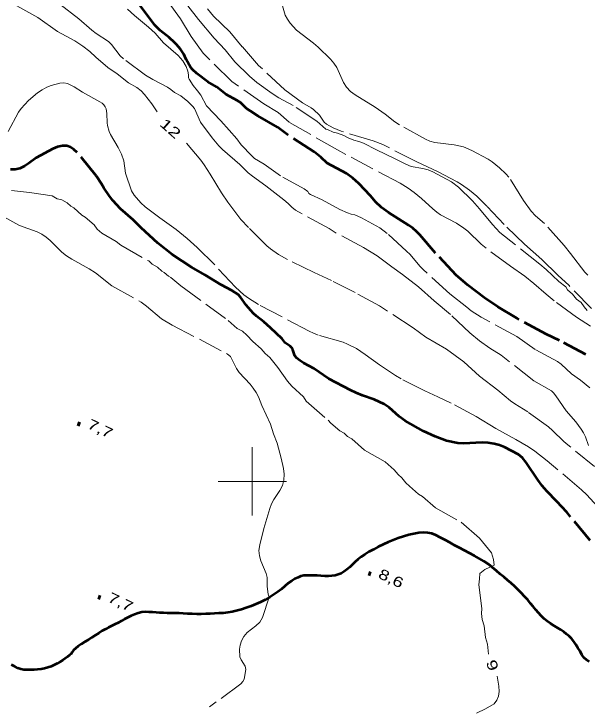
# Model space of a CAD drawing. Extents: x 355726 to 357533, y 5103782 to 5105258.
# Drawn here: x 356465.1 to 356549, y 5104366.5 to 5104468.4 of the extents above; entities that cross this region are included whole.
import ezdxf
from ezdxf.enums import TextEntityAlignment as Align

# ---------------------------------------------------------------- set-up
doc = ezdxf.new("R2010")
doc.units = 0
doc.header["$LTSCALE"] = 0.6
doc.linetypes.add('DASH_DOUBLE_DOT', pattern=[9.2, 5, -1.2, 0.3, -1.2, 0.3, -1.2])
doc.linetypes.add('LONG_DASHED', pattern=[7.5, 6, -1.5])
for name, color, linetype, lineweight in [('1', 7, 'LONG_DASHED', 53), ('2', 7, 'LONG_DASHED', 13), ('3', 7, 'Continuous', 140), ('4', 7, 'DASH_DOUBLE_DOT', 53), ('61', 7, 'Continuous', 13)]:
    doc.layers.add(name, color=color, linetype=linetype, lineweight=lineweight)

msp = doc.modelspace()

# ---------------------------------------------------------------- linework, layer by layer
at = {"layer": '1'}
for points in [[(356548.79, 5104418.59), (356544.98, 5104420.61), (356543.02, 5104421.55), (356538.7, 5104423.87), (356535.92, 5104425.55), (356533.98, 5104426.84), (356531.53, 5104428.7), (356529.84, 5104430.19), (356526.82, 5104433.41), (356524.53, 5104436.09), (356524.03, 5104436.59), (356523.49, 5104437.08), (356522.88, 5104437.51), (356519.92, 5104439.36), (356518.9, 5104440.07), (356518.03, 5104440.92), (356517.31, 5104441.78), (356515.6, 5104443.59), (356514.74, 5104444.36), (356513.79, 5104445.07), (356510.98, 5104446.59), (356510.05, 5104447.46), (356509.06, 5104448.24), (356505.04, 5104450.8), (356503.71, 5104451.86), (356500.82, 5104453.5), (356499.69, 5104454.21), (356499.18, 5104454.59), (356498.26, 5104455.45), (356497.8, 5104455.75), (356496.18, 5104456.63), (356494.76, 5104457.73), (356493.51, 5104458.47), (356491.89, 5104459.68), (356491.25, 5104460.28), (356490.98, 5104460.63), (356490.35, 5104461.76), (356489.99, 5104462.51), (356489.52, 5104463.23), (356488.94, 5104463.92), (356488.6, 5104464.25), (356487.84, 5104464.95), (356486.55, 5104465.99), (356485.76, 5104466.76), (356481.4, 5104472.57)], [(356549.47, 5104391.34), (356546.02, 5104395.48), (356544.58, 5104397.07), (356543.11, 5104398.55), (356542.42, 5104399.36), (356541.78, 5104400.21), (356540.09, 5104402.78), (356539.55, 5104403.44), (356538.96, 5104403.93), (356536.93, 5104404.99), (356536.2, 5104405.3), (356535.39, 5104405.49), (356534.54, 5104405.63), (356533.65, 5104405.68), (356530.91, 5104405.54), (356530.08, 5104405.59), (356528.44, 5104405.95), (356526.75, 5104406.55), (356525.08, 5104407.34), (356522.36, 5104408.88), (356521.48, 5104409.51), (356520.02, 5104410.8), (356519.31, 5104411.3), (356517.85, 5104411.99), (356516.11, 5104412.59), (356515.21, 5104412.94), (356514.36, 5104413.34), (356511.23, 5104415.01), (356509, 5104416.5), (356507.55, 5104417.3), (356506.98, 5104417.67), (356506.52, 5104418.01), (356506.22, 5104418.38), (356505.92, 5104419.24), (356505.75, 5104419.58), (356505.56, 5104419.8), (356504.83, 5104420.3), (356504.37, 5104420.84), (356502.68, 5104422.46), (356501.7, 5104423.33), (356500.6, 5104424.16), (356500.14, 5104424.61), (356499.13, 5104425.8), (356498.3, 5104426.98), (356497.92, 5104427.34), (356497.03, 5104427.92), (356495.47, 5104428.75), (356493.08, 5104430.25), (356491.12, 5104431.33), (356488.29, 5104433.18), (356486.19, 5104434.88), (356483.76, 5104437.09), (356482.59, 5104438.26), (356480.71, 5104439.91), (356479.6, 5104441.09), (356479.1, 5104441.72), (356478.26, 5104442.96), (356477.94, 5104443.55), (356477.22, 5104444.65), (356474.39, 5104448.13), (356473.91, 5104448.59), (356473.4, 5104448.92), (356472.85, 5104449.09), (356472.23, 5104449.09), (356471.51, 5104448.96), (356470.82, 5104448.69), (356468.37, 5104447.34), (356467.28, 5104446.5), (356466.68, 5104446.12), (356466.01, 5104445.79), (356465.33, 5104445.62), (356464.63, 5104445.65)]]:
    msp.add_lwpolyline(points, dxfattribs=at)
at = {"layer": '2'}
for points in [[(356486.07, 5104454.09), (356485.29, 5104455.23), (356484.22, 5104456.63), (356483.75, 5104457.17), (356483.1, 5104457.63), (356481.87, 5104458.34), (356480.21, 5104459.66), (356478.88, 5104460.59), (356477.13, 5104462.08), (356476.24, 5104462.9), (356475.19, 5104463.7), (356474.02, 5104464.46), (356471.52, 5104465.84), (356468.63, 5104467.9), (356465.56, 5104469.61)], [(356549.2, 5104405.26), (356548.75, 5104406.51), (356548.47, 5104407.09), (356548.14, 5104407.63), (356547.33, 5104408.72), (356545.92, 5104410.34), (356544.42, 5104412.54), (356544.08, 5104412.97), (356543.78, 5104413.26), (356541.21, 5104414.73), (356537.18, 5104417.88), (356536.4, 5104418.45), (356534.75, 5104419.51), (356533.25, 5104420.59), (356531.86, 5104421.76), (356528.99, 5104424.42), (356526.62, 5104426.41), (356524.33, 5104428.48), (356522, 5104430.29), (356520.45, 5104431.38), (356518.3, 5104433), (356516.28, 5104434.23), (356512.3, 5104436.34), (356511.25, 5104437.01), (356506.32, 5104439.69), (356505.78, 5104440.13), (356505.24, 5104440.68), (356504.62, 5104441.22), (356502, 5104443.24), (356500.03, 5104444.65), (356499.4, 5104445.17), (356498.18, 5104446.37), (356495.64, 5104448.55), (356495.09, 5104449.09), (356494.13, 5104450.29), (356492.42, 5104452.57), (356491.56, 5104454.57), (356491.27, 5104454.92), (356490.56, 5104455.61), (356489.55, 5104456.41), (356488.63, 5104456.9), (356488.1, 5104457.37), (356487.6, 5104457.68), (356485.46, 5104458.82), (356484.37, 5104459.47), (356481.18, 5104461.84), (356480.69, 5104462.3), (356479.42, 5104463.95), (356478.96, 5104464.37), (356477.16, 5104465.55), (356476.52, 5104466.05), (356474.64, 5104467.69), (356471.84, 5104469.83)], [(356549.49, 5104422.73), (356547.44, 5104424.04), (356544.18, 5104426.43), (356542.99, 5104427.38), (356541.19, 5104428.96), (356539.88, 5104430.03), (356537.8, 5104431.49), (356534.22, 5104434.11), (356533.49, 5104434.73), (356531.54, 5104436.62), (356530.97, 5104437.07), (356529.88, 5104437.79), (356527.56, 5104439.03), (356526.99, 5104439.42), (356526.43, 5104439.87), (356524.78, 5104441.42), (356523.7, 5104442.29), (356522.82, 5104442.9), (356521.63, 5104443.62), (356512.48, 5104448.51), (356505.38, 5104452.58), (356503.8, 5104453.98), (356501.7, 5104455.26), (356497, 5104458.54), (356492.81, 5104462.69), (356491.07, 5104465.09), (356489.51, 5104467.71), (356487.69, 5104470.17)], [(356549.03, 5104425), (356548.56, 5104425.54), (356548.13, 5104426.16), (356547.46, 5104426.69), (356546.86, 5104427.38), (356546.14, 5104428.04), (356545.87, 5104428.46), (356544.84, 5104429.26), (356543.01, 5104431), (356542.06, 5104431.8), (356536.25, 5104436.42), (356535.15, 5104437.58), (356533.26, 5104439.91), (356532.25, 5104441.04), (356530.2, 5104443.04), (356529.18, 5104443.83), (356526.41, 5104445.3), (356525.72, 5104445.61), (356524.96, 5104445.8), (356523.27, 5104446.09), (356522.45, 5104446.41), (356520.93, 5104447.22), (356518.16, 5104448.5), (356516.27, 5104449.51), (356515.59, 5104449.76), (356514.86, 5104449.92), (356514.05, 5104450.26), (356513.42, 5104450.63), (356512.48, 5104450.96), (356511.82, 5104451.11), (356511, 5104451.51), (356510.78, 5104451.57), (356509.45, 5104452.71), (356506, 5104455), (356503.91, 5104456.15), (356502.91, 5104456.76), (356500.67, 5104458.36), (356499.59, 5104459.29), (356497.44, 5104461.42), (356496.02, 5104463.15), (356494.44, 5104464.88), (356492.12, 5104467.61), (356490.58, 5104469.59)], [(356525.34, 5104450.09), (356521.57, 5104452.16), (356520.86, 5104452.63), (356519.46, 5104453.75), (356518, 5104454.75), (356515.08, 5104456.59), (356514.39, 5104457.07), (356513.8, 5104457.69), (356513.37, 5104458.37), (356512.38, 5104460.57), (356511.94, 5104461.2), (356511.44, 5104461.79), (356509.64, 5104463.53), (356508.98, 5104464.11), (356506.48, 5104466.04), (356505.54, 5104467.08), (356505.15, 5104467.63), (356504.84, 5104468.21), (356504.33, 5104469.94)], [(356549.4, 5104413.7), (356548.03, 5104414.79), (356546.72, 5104415.72), (356545.2, 5104417.13), (356544.68, 5104417.54), (356541.42, 5104419.32), (356538.7, 5104421.2), (356533.51, 5104424.01), (356532.04, 5104424.98), (356531.38, 5104425.49), (356528.93, 5104427.45), (356525, 5104430.99), (356524.5, 5104431.5), (356523.1, 5104433.18), (356522.58, 5104433.7), (356519.73, 5104436.29), (356518.68, 5104437.13), (356515.99, 5104438.59), (356515, 5104439.01), (356514.48, 5104439.11), (356513.94, 5104439.29), (356512.81, 5104439.8), (356510.22, 5104441.21), (356508.53, 5104441.99), (356508.28, 5104442.13), (356508.11, 5104442.41), (356507.62, 5104442.8), (356504.14, 5104444.71), (356501.74, 5104446.43), (356500.33, 5104447.26), (356499.93, 5104447.62), (356498.4, 5104449.23), (356497.73, 5104450.13), (356496.62, 5104451.41), (356495.41, 5104452.76), (356493.31, 5104454.98), (356492.47, 5104456.53), (356492.01, 5104457.17), (356491.35, 5104457.95), (356490.78, 5104458.84), (356490.66, 5104459.08), (356490.67, 5104459.51), (356490.56, 5104460.03), (356490.31, 5104460.73), (356489.84, 5104461.53), (356489.15, 5104462.34), (356487.02, 5104464.2), (356485.79, 5104465.58), (356484.83, 5104466.45), (356482.76, 5104468.18), (356481.75, 5104469.09)], [(356549.62, 5104425.3), (356546.36, 5104428.67), (356544.7, 5104430.18), (356542.38, 5104432.45), (356539.85, 5104434.71), (356536.84, 5104437.59), (356534.31, 5104440.28), (356532.84, 5104441.72), (356531.8, 5104442.62), (356530.62, 5104443.46), (356529.98, 5104443.86), (356527.11, 5104445.37), (356524.09, 5104446.75), (356519.13, 5104449.28), (356517.67, 5104449.83), (356513, 5104451.26), (356511.85, 5104451.76), (356510.86, 5104452.3), (356510.5, 5104452.55), (356509.86, 5104453.59), (356508.98, 5104454.4), (356508.62, 5104454.67), (356507.33, 5104455.38), (356504.79, 5104457.3), (356500.93, 5104460.88), (356498.53, 5104463.61), (356496.73, 5104465.8), (356494.32, 5104468.07), (356493.43, 5104469.15)], [(356482.35, 5104442.51), (356481.43, 5104445.09), (356481.2, 5104446.91), (356480.87, 5104447.88), (356480.4, 5104448.88), (356479.27, 5104450.78), (356479.08, 5104451.21), (356478.84, 5104452.07), (356478.78, 5104452.46), (356478.73, 5104453.84), (356478.62, 5104454.51), (356478.48, 5104454.82), (356478.27, 5104455.09), (356478.02, 5104455.37), (356477.72, 5104455.57), (356475.15, 5104456.94), (356473.93, 5104457.74), (356472.99, 5104458.24), (356472.45, 5104458.34), (356471.85, 5104458.28), (356470.59, 5104457.94), (356469.92, 5104457.68), (356469.25, 5104457.3), (356468.58, 5104456.84), (356467.26, 5104455.76), (356466.19, 5104454.59), (356465.8, 5104454.05), (356464.3, 5104451.22)], [(356549.13, 5104430.17), (356548.68, 5104430.61), (356546.58, 5104433.36), (356545.63, 5104434.51), (356542.75, 5104437.73), (356541.47, 5104438.88), (356540.82, 5104439.55), (356539.7, 5104441.12), (356537.57, 5104444.51), (356537.13, 5104445.03), (356536.19, 5104445.91), (356535.1, 5104446.78), (356534.51, 5104447.17), (356532.13, 5104448.43), (356530.9, 5104448.97), (356529.56, 5104449.26), (356526.71, 5104449.59), (356526.01, 5104449.78), (356525.34, 5104450.09)], [(356502.68, 5104434.03), (356502.15, 5104434.46), (356499.45, 5104437.15), (356498.34, 5104438.34), (356496.44, 5104440.88), (356495.52, 5104442.22), (356493.86, 5104444.98), (356492.95, 5104446.33), (356492.47, 5104446.99), (356490.39, 5104449.48)], [(356455.73, 5104442.98), (356465.85, 5104437.51), (356466.46, 5104437.23), (356468.53, 5104436.51), (356469.2, 5104436.19), (356469.84, 5104435.76), (356470.41, 5104435.26), (356472.16, 5104433.53), (356472.84, 5104433), (356473.6, 5104432.5), (356476.16, 5104431.09), (356477.04, 5104430.51), (356479.47, 5104428.62), (356483.74, 5104426.21), (356484.53, 5104425.63), (356486.71, 5104423.8), (356488.27, 5104422.88), (356496.4, 5104418.63), (356496.82, 5104418.26), (356497.7, 5104416.54), (356498.1, 5104415.94), (356499.68, 5104414.22), (356500.15, 5104413.63), (356500.58, 5104413), (356500.92, 5104412.36), (356501.4, 5104411.11), (356502.66, 5104408.37), (356503.12, 5104406.95), (356503.65, 5104405.58), (356504.25, 5104403.41), (356504.59, 5104401.87)], [(356464.77, 5104442.57), (356467.4, 5104442.28), (356470.72, 5104441.8), (356471.47, 5104441.37), (356472.16, 5104441.18), (356472.92, 5104440.76), (356473.44, 5104440.27), (356473.89, 5104440.01), (356475.08, 5104438.95), (356475.53, 5104438.69), (356476.88, 5104437.54), (356477.31, 5104436.9), (356477.98, 5104436.32), (356480.1, 5104435.13), (356480.77, 5104434.55), (356484.85, 5104432.26), (356485.37, 5104431.77), (356486.12, 5104431.34), (356486.79, 5104430.76), (356487.1, 5104430.59), (356487.77, 5104430.02), (356488.07, 5104429.85), (356489.56, 5104428.61), (356496.46, 5104423.54), (356497.8, 5104422.39), (356498.56, 5104421.96), (356499.23, 5104421.39), (356500.11, 5104420.49), (356501.3, 5104419.42), (356501.89, 5104418.7), (356502.56, 5104418.12), (356503.73, 5104416.67), (356505.18, 5104414.66)], [(356551, 5104395.79), (356548.95, 5104398.05), (356548.17, 5104398.76), (356543.14, 5104403.03), (356541.33, 5104404.43), (356540.4, 5104405.05), (356538.57, 5104406.15), (356535.62, 5104407.76), (356532.79, 5104409.49), (356529.11, 5104411.45), (356527.18, 5104412.38), (356525.25, 5104413.24), (356521.78, 5104415.01), (356520.95, 5104415.49), (356518.61, 5104417.04), (356516.51, 5104418.59), (356515.24, 5104419.43), (356513.96, 5104420.09), (356513.28, 5104420.38), (356509.65, 5104421.42), (356508.97, 5104421.67), (356508.34, 5104421.97), (356500.9, 5104425.88), (356499.47, 5104426.79), (356498.79, 5104427.3), (356497.54, 5104428.44), (356494.51, 5104431.69), (356491.95, 5104434.24), (356490.48, 5104435.54), (356488.86, 5104436.84), (356486.47, 5104438.55), (356484.31, 5104440.19), (356483.72, 5104440.75), (356482.71, 5104441.88), (356482.35, 5104442.51)], [(356550.1, 5104402.18), (356546.17, 5104405.36), (356545.61, 5104405.84), (356543.93, 5104407.46), (356543.34, 5104407.96), (356540.31, 5104410.2), (356538.43, 5104411.34), (356537.81, 5104411.8), (356535.96, 5104413.34), (356533.27, 5104415.42), (356530.96, 5104417.48), (356528.42, 5104419.33), (356525.42, 5104421.11), (356523.57, 5104422.46), (356518.61, 5104425.71), (356515.06, 5104427.62), (356511.59, 5104429.41), (356509.08, 5104430.55), (356505.15, 5104432.48), (356503.84, 5104433.22), (356502.68, 5104434.03)], [(356505.18, 5104414.66), (356505.77, 5104413.93), (356507.48, 5104412.38), (356507.91, 5104411.73), (356511.11, 5104408.94), (356511.48, 5104408.53), (356512.82, 5104407.38), (356513.43, 5104407.04), (356513.95, 5104406.55), (356514.55, 5104406.21), (356516.41, 5104404.57), (356519.44, 5104402.87), (356520.78, 5104401.71), (356521.36, 5104400.99), (356521.88, 5104400.5), (356522.47, 5104399.77), (356522.99, 5104399.28), (356524.33, 5104398.13), (356524.93, 5104397.79), (356526.8, 5104396.15), (356530.58, 5104394.02), (356533.26, 5104391.71), (356535.01, 5104389.53), (356535.28, 5104388.59), (356535.39, 5104387.74), (356534.04, 5104387.11), (356533.31, 5104386.53), (356533.27, 5104385.76), (356533.14, 5104384.84), (356533.59, 5104381.41), (356533.55, 5104380.64), (356533.66, 5104379.78), (356533.93, 5104378.84), (356534.15, 5104377.13), (356534.41, 5104376.19), (356534.57, 5104374.71)], [(356504.59, 5104401.87), (356504.67, 5104401.04), (356504.63, 5104400.19), (356504.41, 5104399.38), (356504.03, 5104398.65), (356503.18, 5104397.36), (356502.83, 5104396.72), (356502.56, 5104396.05), (356501.68, 5104393.09), (356501.1, 5104390.73), (356500.98, 5104389.88), (356501.06, 5104389.11), (356501.26, 5104388.38), (356502.05, 5104386.51), (356502.18, 5104385.92), (356502.17, 5104384.63), (356502.35, 5104383.5), (356502.49, 5104383.04), (356501.5, 5104380.07), (356501.11, 5104379.41), (356500.53, 5104378.87), (356499.27, 5104377.87), (356498.77, 5104377.3), (356498.44, 5104376.68), (356498.24, 5104376.03), (356498.13, 5104375.42), (356498.2, 5104374.3), (356498.37, 5104373.88), (356498.94, 5104372.97), (356499.05, 5104372.47), (356498.84, 5104371.04), (356498.64, 5104370.7), (356498.34, 5104370.38), (356493.76, 5104367.01)], [(356532.82, 5104366.09), (356534.13, 5104366.72), (356535.39, 5104367.45), (356535.79, 5104367.96), (356536.02, 5104368.55), (356536.13, 5104369.26), (356536.1, 5104370.05), (356535.82, 5104371.48)]]:
    msp.add_lwpolyline(points, dxfattribs=at)
at = {"layer": '3'}
for p, q in [((356474.45, 5104408.49), (356474.81, 5104408.32)), ((356517.01, 5104386.58), (356517.37, 5104386.41)), ((356477.44, 5104383.11), (356477.8, 5104382.94))]:
    msp.add_line(p, q, dxfattribs=at)
at = {"layer": '4'}
for points in [[(356549.33, 5104373.66), (356548.93, 5104373.87), (356548.55, 5104374.19), (356548.24, 5104374.63), (356547.96, 5104375.13), (356547.66, 5104375.65), (356547.37, 5104376.13), (356547.06, 5104376.59), (356546.74, 5104376.99), (356546.38, 5104377.34), (356546, 5104377.66), (356545.58, 5104377.98), (356545.14, 5104378.28), (356544.66, 5104378.57), (356544.17, 5104378.88), (356543.65, 5104379.22), (356543.16, 5104379.55), (356542.72, 5104379.9), (356542.29, 5104380.3), (356541.88, 5104380.75), (356541.48, 5104381.21), (356541.11, 5104381.68), (356540.73, 5104382.13), (356540.32, 5104382.65), (356539.85, 5104383.16), (356539.36, 5104383.67), (356538.86, 5104384.18), (356538.37, 5104384.65), (356537.87, 5104385.09), (356537.35, 5104385.55), (356536.85, 5104385.99), (356536.29, 5104386.44), (356535.74, 5104386.9), (356535.16, 5104387.38), (356534.56, 5104387.88), (356533.91, 5104388.34), (356533.22, 5104388.72), (356532.51, 5104389.09), (356531.8, 5104389.48), (356531.07, 5104389.87), (356530.34, 5104390.25), (356529.64, 5104390.63), (356528.9, 5104391.04), (356528.2, 5104391.43), (356527.51, 5104391.8), (356526.88, 5104392.12), (356526.28, 5104392.38), (356525.68, 5104392.49), (356525.03, 5104392.51), (356524.36, 5104392.47), (356523.65, 5104392.34), (356522.89, 5104392.18), (356522.14, 5104391.93), (356521.36, 5104391.68), (356520.61, 5104391.4), (356519.88, 5104391.11), (356519.14, 5104390.76), (356518.42, 5104390.4), (356517.73, 5104390.05), (356517.08, 5104389.7), (356516.46, 5104389.3), (356515.94, 5104388.94), (356515.45, 5104388.59), (356515.04, 5104388.21), (356514.65, 5104387.83), (356514.26, 5104387.45), (356513.84, 5104387.09), (356513.43, 5104386.79), (356513.01, 5104386.54), (356512.57, 5104386.36), (356512.13, 5104386.23), (356511.64, 5104386.17), (356511.15, 5104386.15), (356510.62, 5104386.15), (356510.06, 5104386.16), (356509.48, 5104386.21), (356508.9, 5104386.23), (356508.39, 5104386.23), (356507.94, 5104386.24), (356507.55, 5104386.21), (356507.13, 5104386.11), (356506.7, 5104385.94), (356506.25, 5104385.73), (356505.78, 5104385.45), (356505.27, 5104385.11), (356504.78, 5104384.67), (356504.26, 5104384.24), (356503.74, 5104383.82), (356503.16, 5104383.43), (356502.56, 5104383.03), (356501.89, 5104382.67)], [(356501.89, 5104382.67), (356501.22, 5104382.34), (356500.53, 5104382.04), (356499.83, 5104381.76), (356499.13, 5104381.48), (356498.42, 5104381.25), (356497.07, 5104380.91), (356496.41, 5104380.8), (356495.74, 5104380.73), (356495.09, 5104380.7), (356494.47, 5104380.67), (356493.84, 5104380.62), (356493.19, 5104380.61), (356492.54, 5104380.59), (356491.87, 5104380.59), (356491.2, 5104380.61), (356490.54, 5104380.62), (356489.9, 5104380.66), (356489.29, 5104380.7), (356488.69, 5104380.71), (356488.13, 5104380.71), (356487.55, 5104380.73), (356486.99, 5104380.75), (356486.45, 5104380.76), (356485.92, 5104380.8), (356485.4, 5104380.86), (356484.87, 5104380.88), (356484.34, 5104380.91), (356483.82, 5104380.84), (356483.3, 5104380.72), (356482.78, 5104380.54), (356482.28, 5104380.34), (356481.8, 5104380.08), (356481.33, 5104379.84), (356480.87, 5104379.57), (356480.4, 5104379.3), (356479.94, 5104379.08), (356479.46, 5104378.86), (356478.99, 5104378.63), (356478.51, 5104378.38), (356478.04, 5104378.12), (356477.56, 5104377.8), (356477.06, 5104377.47), (356476.55, 5104377.13), (356476.04, 5104376.82), (356475.51, 5104376.5), (356474.99, 5104376.16), (356474.51, 5104375.86), (356474.12, 5104375.55), (356473.85, 5104375.3), (356473.65, 5104375.01), (356473.49, 5104374.76), (356473.27, 5104374.55), (356472.96, 5104374.33), (356472.61, 5104374.08), (356472.28, 5104373.84), (356471.88, 5104373.59), (356471.47, 5104373.36), (356471.04, 5104373.13), (356470.58, 5104372.92), (356470.1, 5104372.74), (356469.6, 5104372.61), (356469.1, 5104372.5), (356468.58, 5104372.45), (356468.07, 5104372.42), (356467.57, 5104372.4), (356467.08, 5104372.42), (356466.6, 5104372.44), (356466.16, 5104372.53), (356465.7, 5104372.68), (356465.26, 5104372.91), (356464.79, 5104373.16)]]:
    msp.add_lwpolyline(points, dxfattribs=at)
at = {"layer": '61'}
for p, q in [((356500, 5104395), (356500, 5104405)), ((356495, 5104400), (356505, 5104400))]:
    msp.add_line(p, q, dxfattribs=at)

# ---------------------------------------------------------------- texts
at = {"layer": '2'}
for s, rotation, width, p in [('12', 318.485, 1.45, (356487.53, 5104451.09)), ('9', 292.198, 1.4, (356534.44, 5104372.8))]:
    msp.add_text(s, height=1.5, rotation=rotation, dxfattribs=dict(at, width=width)).set_placement(p, align=Align.CENTER)
at = {"layer": '3', "width": 1.35}
for s, p in [('7,7    ', (356475.74, 5104407.86)), ('8,6    ', (356518.3, 5104385.94)), ('7,7    ', (356478.72, 5104382.48))]:
    msp.add_text(s, height=1.5, rotation=334.423, dxfattribs=at).set_placement(p)

doc.saveas('drawing.dxf')
